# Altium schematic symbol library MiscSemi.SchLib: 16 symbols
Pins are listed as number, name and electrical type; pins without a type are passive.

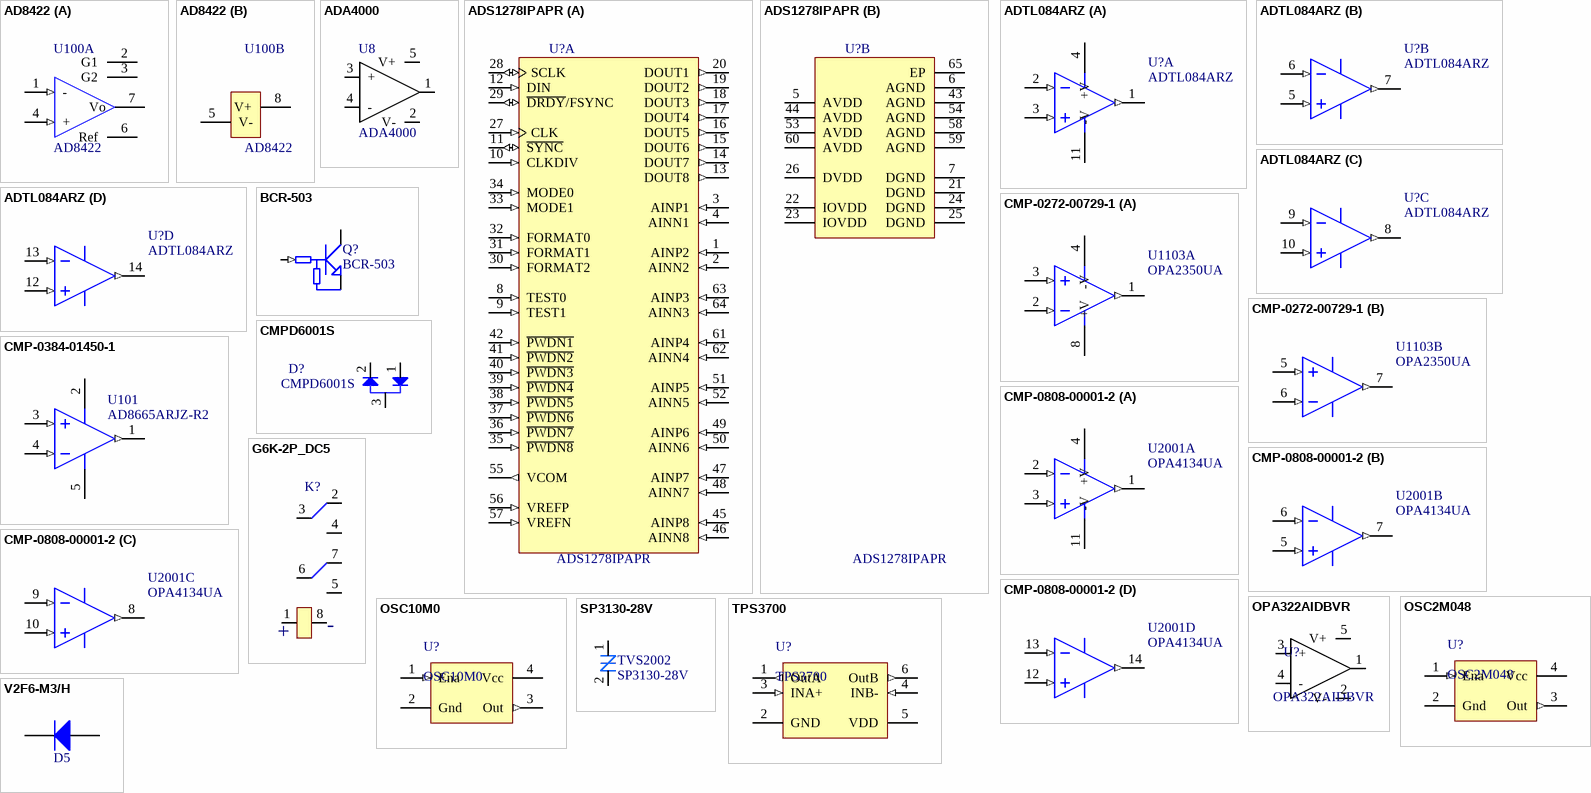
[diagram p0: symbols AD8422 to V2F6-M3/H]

## AD8422
designator U100
IC OPAMP INSTR 2.2MHZ RRO 8SOIC; MFG PN: AD8422ARZ; DK PN: AD8422ARZ-ND; MFG: Analog Devices
footprint MYSO8
part A pins: 1 - (in), 2 G1, 3 G2, 4 + (in), 6 Ref, 7 Vo
part B pins: 5 V- (power), 8 V+ (power)

## ADA4000
designator U8
J-FET Amplifier Circuit - TSOT-5; MFG PN: ADA4000-1AUJZ-R7; DK PN: SOT25-5; MFG: Analog Devices
footprint SOT23-5
pins: 1, 2 V-, 3 +, 4 -, 5 V+

## ADS1278IPAPR
designator U?  Comment_1: ADS1278IPAPR  (hidden comment: *)
Octal, Simultaneous Sampling, 24-Bit ADC, -40 to 105 degC, 64-pin PQFP (PAP64), Green (RoHS & no Sb/Br); MFG: Texas Instruments; DK PN: AD8422ARZ-ND
footprint TI-PAP64-6495X6495TP_N (QFP, 64-Leads, Body 10x10mm, Pitch 0.5mm, Thermal Pad 7x7mm, IPC Medium Density)
footprint TI-PAP64-6495X6495TP_M (QFP, 64-Leads, Body 10x10mm, Pitch 0.5mm, Thermal Pad 7x7mm, IPC Low Density)
footprint TI-PAP64-6495X6495TP_L (QFP, 64-Leads, Body 10x10mm, Pitch 0.5mm, Thermal Pad 7x7mm, IPC High Density)
part A pins: 1 AINP2 (in) "AINP[8:1] Positive analog input, channels 8 through 1.", 2 AINN2 (in) "AINN[8:1] Negative analog input, channels 8 through 1.", 3 AINP1 (in) "AINP[8:1] Positive analog input, channels 8 through 1.", 4 AINN1 (in) "AINN[8:1] Negative analog input, channels 8 through 1.", 8 TEST0 (in) "TEST[1:0] Test mode select: 00 = Normal operation 01 = Do not use 11 = Test mode 10 = Do not use", 9 TEST1 (in) "TEST[1:0] Test mode select: 00 = Normal operation 01 = Do not use 11 = Test mode 10 = Do not use", 10 CLKDIV (in) "CLK input divider control:1 = 37MHz (High-Speed mode)/otherwise 27MHz  0 = 13.5MHz (low-power)/5.4MHz (low-speed)", 11 ~{SYNC} (io) "Synchronize input (all channels).", 12 DIN (in) "Daisy-chain data input.", 13 DOUT8 (out) "DOUT[8:1] Data output for channels 8 through 1.", 14 DOUT7 (out) "DOUT[8:1] Data output for channels 8 through 1.", 15 DOUT6 (out) "DOUT[8:1] Data output for channels 8 through 1.", 16 DOUT5 (out) "DOUT[8:1] Data output for channels 8 through 1.", 17 DOUT4 (out) "DOUT[8:1] Data output for channels 8 through 1.", 18 DOUT3 (out) "DOUT[8:1] Data output for channels 8 through 1.", 19 DOUT2 (out) "DOUT[8:1] Data output for channels 8 through 1.", 20 DOUT1 (out) "DOUT[8:1] Data output for channels 8 through 1.", 27 CLK (in) "Master clock input (fCLK).", 28 SCLK (io) "Serial clock input, Modulator clock output", 29 ~{DRDY}/FSYNC (io) "Frame-Sync protocol: frame clock input; SPI protocol: data ready output.", 30 FORMAT2 (in) "FORMAT[2:0] Selects Frame-Sync/SPI protocol, TDM/discrete data outputs, fixed/dynamic position TDM data, and modulator mode/normal operating mode.", 31 FORMAT1 (in) "FORMAT[2:0] Selects Frame-Sync/SPI protocol, TDM/discrete data outputs, fixed/dynamic position TDM data, and modulator mode/normal operating mode.", 32 FORMAT0 (in) "FORMAT[2:0] Selects Frame-Sync/SPI protocol, TDM/discrete data outputs, fixed/dynamic position TDM data, and modulator mode/normal operating mode.", 33 MODE1 (in) "MODE[1:0] Selects High-Speed, High-Resolution, Low-Power, or Low-Speed mode operation.", 34 MODE0 (in) "MODE[1:0] Selects High-Speed, High-Resolution, Low-Power, or Low-Speed mode operation.", 35 ~{PWDN8} (in) "P\W\D\N\[8:1] Power-down control for channels 8 through 1.", 36 ~{PWDN7} (in) "P\W\D\N\[8:1] Power-down control for channels 8 through 1.", 37 ~{PWDN6} (in) "P\W\D\N\[8:1] Power-down control for channels 8 through 1.", 38 ~{PWDN5} (in) "P\W\D\N\[8:1] Power-down control for channels 8 through 1.", 39 ~{PWDN4} (in) "P\W\D\N\[8:1] Power-down control for channels 8 through 1.", 40 ~{PWDN3} (in) "P\W\D\N\[8:1] Power-down control for channels 8 through 1.", 41 ~{PWDN2} (in) "P\W\D\N\[8:1] Power-down control for channels 8 through 1.", 42 ~{PWDN1} (in) "P\W\D\N\[8:1] Power-down control for channels 8 through 1.", 45 AINP8 (in) "AINP[8:1] Positive analog input, channels 8 through 1.", 46 AINN8 (in) "AINN[8:1] Negative analog input, channels 8 through 1.", 47 AINP7 (in) "AINP[8:1] Positive analog input, channels 8 through 1.", 48 AINN7 (in) "AINN[8:1] Negative analog input, channels 8 through 1.", 49 AINP6 (in) "AINP[8:1] Positive analog input, channels 8 through 1.", 50 AINN6 (in) "AINN[8:1] Negative analog input, channels 8 through 1.", 51 AINP5 (in) "AINP[8:1] Positive analog input, channels 8 through 1.", 52 AINN5 (in) "AINN[8:1] Negative analog input, channels 8 through 1.", 55 VCOM (out) "AVDD/2 Unbuffered voltage output.", 56 VREFP (in) "Positive reference input.", 57 VREFN (in) "Negative reference input.", 61 AINP4 (in) "AINP[8:1] Positive analog input, channels 8 through 1.", 62 AINN4 (in) "AINN[8:1] Negative analog input, channels 8 through 1.", 63 AINP3 (in) "AINP[8:1] Positive analog input, channels 8 through 1.", 64 AINN3 (in) "AINN[8:1] Negative analog input, channels 8 through 1."
part B pins: 5 AVDD (power) "Analog power supply (4.75V to 5.25V).", 6 AGND (power) "Analog ground; connect to DGND using a single plane.", 7 DGND (power) "Digital ground power supply.", 21 DGND (power) "Digital ground power supply.", 22 IOVDD (power) "I/O power supply (+1.65V to +3.6V)", 23 IOVDD (power) "I/O power supply (+1.65V to +3.6V)", 24 DGND (power) "Digital ground power supply.", 25 DGND (power) "Digital ground power supply.", 26 DVDD (power) "Digital core power supply", 43 AGND (power) "Analog ground; connect to DGND using a single plane.", 44 AVDD (power) "Analog power supply (4.75V to 5.25V).", 53 AVDD (power) "Analog power supply (4.75V to 5.25V).", 54 AGND (power) "Analog ground; connect to DGND using a single plane.", 58 AGND (power) "Analog ground; connect to DGND using a single plane.", 59 AGND (power) "Analog ground; connect to DGND using a single plane.", 60 AVDD (power) "Analog power supply (4.75V to 5.25V).", 65 EP

## ADTL084ARZ
designator U?
J-FET Amplifier 4 Circuit 14-SOIC; MFG: Analog Devices; MFG PN: OPA4134UA
footprint SO14
part A pins: 1 OUT A (out), 2 IN A- (in), 3 IN A+ (in), 4 +V (power), 11 -V (power)
part B pins: 5 IN B+ (in), 6 IN B- (in), 7 OUT B (out)
part C pins: 8 OUT C (out), 9 IN C- (in), 10 IN C+ (in)
part D pins: 12 IN D+ (in), 13 IN D- (in), 14 OUT D (out)

## BCR-503
designator Q?
TRANSISTOR NPN DGTL 50V SOT-23; MFG: Infineon; MFG PN: BCR 503 E6327; DK PN: BCR503E6327INDKR-ND
footprint SOT-23
pins: 1 BASE (in), 2 EMITTER, 3 COLLECTOR

## CMP-0272-00729-1
designator U1103, comment OPA2350UA
High-Speed, Single-Supply, Rail-to-Rail Operational Amplifier MicroAmplifier(TM) Series, 2.7 to 5.5 V, -40 to 85 degC, 8-pin SOIC (D8), Green (RoHS & no Sb/Br); MFG: Texas Instruments; DK PN: OPA2350UA-ND
footprint TI-D8_M (SOIC, 8-Leads, Body 4.9x3.9mm, Pitch 1.27mm, IPC Low Density)
footprint TI-D8_L (SOIC, 8-Leads, Body 4.9x3.9mm, Pitch 1.27mm, IPC High Density)
footprint TI-D8_N (SOIC, 8-Leads, Body 4.9x3.9mm, Pitch 1.27mm, IPC Medium Density)
part A pins: 1 OUT A (out), 2 IN A- (in), 3 IN A+ (in), 4 -V (power), 8 +V (power)
part B pins: 5 IN B+ (in), 6 IN B- (in), 7 OUT B (out)

## CMP-0384-01450-1
designator U101  Comment_1: AD8665ARJZ-R2  (hidden comment: CMP-0384-01450-1)
Single Channel Wide Bandwidth Operational Amplifier, 4 MHz BW, 3.5 V/us SR, Industrial, 5-pin SOT23 (RJ-5), Reel; MFG: Analog Devices; DK PN: Surface Mount
footprint ADI-RJ-5_M (SOT-23, 5-Leads, Body 2.9x1.6mm, Pitch 0.95mm, IPC Low Density)
footprint ADI-RJ-5_L (SOT-23, 5-Leads, Body 2.9x1.6mm, Pitch 0.95mm, IPC High Density)
footprint ADI-RJ-5_N (SOT-23, 5-Leads, Body 2.9x1.6mm, Pitch 0.95mm, IPC Medium Density)
pins: 1 OUT (out), 2 -V (power), 3 +IN (in), 4 -IN (in), 5 +V (power)

## CMP-0808-00001-2
designator U2001  Comment_1: OPA4134UA  (hidden comment: *)
SoundPlus(TM) High Performance Audio Operational Amplifier, 5 to 36 V, -55 to 125 degC, 14-pin SOIC (D14), Green (RoHS & no Sb/Br); DK PN: OPA4134UA-ND; MFG: Texas Instruments
footprint D0014A_N (SOIC, 14-Leads, Body 8.75x4mm, Pitch 1.27mm, IPC Medium Density)
footprint D0014A_L (SOIC, 14-Leads, Body 8.75x4mm, Pitch 1.27mm, IPC High Density)
footprint D0014A_M (SOIC, 14-Leads, Body 8.75x4mm, Pitch 1.27mm, IPC Low Density)
part A pins: 1 OUT A (out), 2 IN A- (in), 3 IN A+ (in), 4 +V (power), 11 -V (power)
part B pins: 5 IN B+ (in), 6 IN B- (in), 7 OUT B (out)
part C pins: 8 OUT C (out), 9 IN C- (in), 10 IN C+ (in)
part D pins: 12 IN D+ (in), 13 IN D- (in), 14 OUT D (out)

## CMPD6001S
designator D?
Diode Array 1 Pair Series Connection Standard 75V 250mA Surface Mount TO-236-3, SC-59, SOT-23-3; MFG PN: CMPD6001S TR; DK PN: CMPD6001S CT-ND; MFG: Central Semiconductor
footprint SOT-23
pins: 1, 2, 3

## G6K-2P_DC5
designator K?  (value not drawn)
Telecom Relay DPDT (2 Form C) Through Hole; MFG PN: G6K-2P DC5; DK PN: Z116-ND; MFG: Omron
footprint G6K-2P
pins: 1, 2, 3, 4, 5, 6, 7, 8

## OPA322AIDBVR
designator U?
General Purpose Amplifier 1 Circuit Rail-to-Rail SOT-23-5; DK PN: SOT25-5; MFG: TI
footprint SOT23-5
pins: 1, 2 V-, 3 +, 4 -, 5 V+

## OSC2M048
designator U?
2.048MHz CMOS XO (Standard) Oscillator Surface Mount 3.3V 9mA Enable/Disable; MFG PN: SG-615P 2.0480MC0:ROHS; DK PN: SER2218CT-ND; MFG: Epson
footprint OSC4
pins: 1 Ena (in), 2 Gnd (power), 3 Out (out), 4 Vcc (power)
1 alternate drawing of the same symbol

## OSC10M0
designator U?
10MHz CMOS XO (Standard) Oscillator Surface Mount 3.3V 9mA Enable/Disable; MFG PN: ECS-8FA3X-100-TR; DK PN: XC1639CT-ND; MFG: ECS Inc.
footprint OSC4
pins: 1 Ena (in), 2 Gnd (power), 3 Out (out), 4 Vcc (power)
1 alternate drawing of the same symbol

## SP3130-28V
designator TVS2002
TVS DIODES 28VWM 48VC SOD882; MFG PN: SP3130-01ETG; DK PN: F7505TR-ND; MFG: Littlefuse
footprint SOD882
pins: 1, 2

## TPS3700
designator U?
IC COMP WINDOW W/REF 6SOT; MFG PN: TPS3700DDCR; DK PN: 296-30395-2-ND; MFG: Texas Instruments
footprint SOT23-6
pins: 1 OutA (out), 2 GND (power), 3 INA+ (in), 4 INB- (in), 5 VDD (power), 6 OutB (out)

## V2F6-M3/H
designator D5, comment Diode  (value not drawn)
Diode Schottky 60V 2A Surface Mount DO-219AB (SMF); MFG PN: V2F6-M3/H; DK PN: V2F6-M3/HGICT-ND; MFG: Vishay
footprint DO219AB
pins: 1 A, 2 K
